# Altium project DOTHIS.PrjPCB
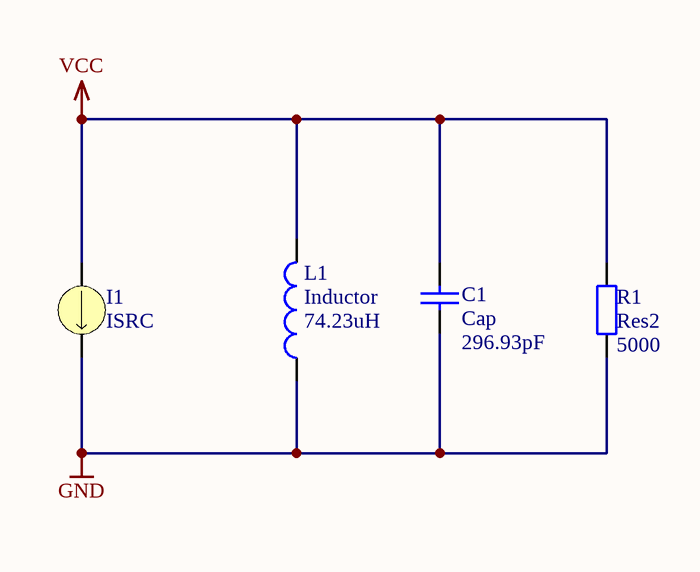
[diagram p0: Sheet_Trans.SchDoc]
2 sheets, 8 parts. Net scope: global (net labels, ports and power ports of the same name join across sheets).
Sheets:
  Sheet_Trans.SchDoc
  Sheet_AC.SchDoc

## Sheet Sheet_Trans.SchDoc
size A4

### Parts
C1  Cap  value 296.93pF  [RAD-0.3]
I1  ISRC
L1  Inductor  value 74.23uH  [0402-A]
R1  Res2  value 5000  [AXIAL-0.4]

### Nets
GND: C1.1 I1.2 L1.1 R1.1
VCC: C1.2 I1.1 L1.2 R1.2

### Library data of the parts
C1 = Cap: Capacitor
I1 = ISRC: Current Source; Note: PCB Footprint - Not required; Value: 1mA
L1 = Inductor: Code_IEC: 1005
R1 = Res2: Resistor

## Sheet Sheet_AC.SchDoc
size A4
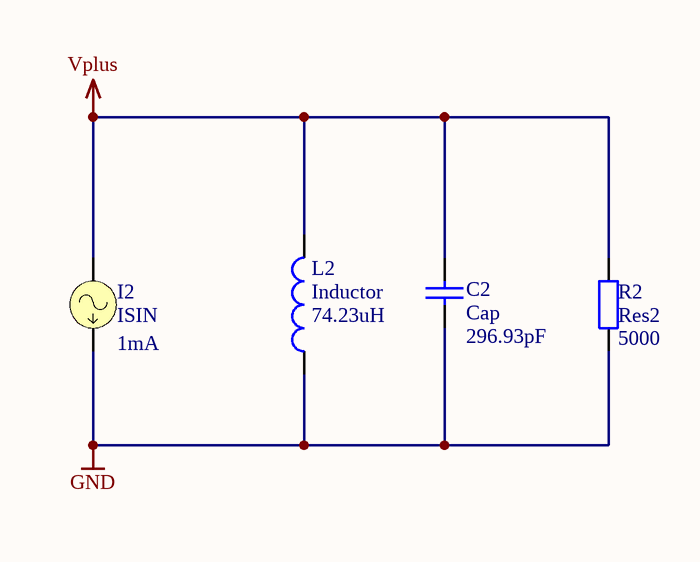
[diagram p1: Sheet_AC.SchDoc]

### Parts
C2  Cap  value 296.93pF  [RAD-0.3]
I2  ISIN  Amplitude: 1mA
L2  Inductor  value 74.23uH  [0402-A]
R2  Res2  value 5000  [AXIAL-0.4]

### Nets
GND: C2.1 I2.2 L2.1 R2.1
Vplus: C2.2 I2.1 L2.2 R2.2

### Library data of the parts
C2 = Cap: Capacitor
I2 = ISIN: Sinusoidal Current Source
L2 = Inductor: Code_IEC: 1005
R2 = Res2: Resistor

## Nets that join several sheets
GND: Sheet_Trans (C1.1 I1.2 L1.1 R1.1), Sheet_AC (C2.1 I2.2 L2.1 R2.1)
